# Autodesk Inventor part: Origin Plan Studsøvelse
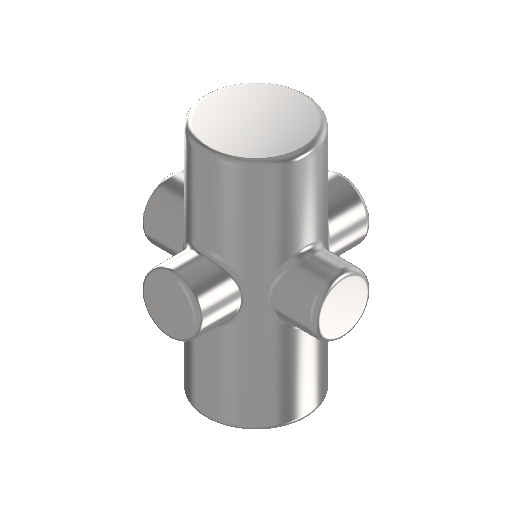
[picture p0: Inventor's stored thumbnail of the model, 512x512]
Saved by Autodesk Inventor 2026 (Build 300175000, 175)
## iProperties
Created: 2004-09
Part Number: Origin Plan Studsøvelse
Document SubType Name: Modeling
Designer: Lars Bertram Pedersen
Manufacturer: Standard
Standards Organization: Custom
Material: Steel, Mild
Density: 7.85 g/cm^3
Appearance: Semi-Polished
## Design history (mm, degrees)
sketch "Sketch1"
  geometry: C1 r 17.5 at (0, 0)
  constraints: 1 centre point
  dimensions: "d0" = 35 diameter of C1
extrude "Extrusion1" new body sketch "Sketch1" stored distance "d1" = 80; taper "d2" = 0 deg
sketch "Sketch2"
  geometry: C1 r 10 at (0, 0); 1 further point
  constraints: 1 centre point, 1 coincident
  dimensions: "d3" = 20 diameter of C1
extrude "Extrusion2" join sketch "Sketch2" stored distance "d4" = 60; taper "d5" = 0 deg
sketch "Sketch3"
  geometry: C1 r 10 at (0, 0); 1 further point
  constraints: 1 centre point, 1 coincident
  dimensions: "d6" = 20 diameter of C1
extrude "Extrusion3" join sketch "Sketch3" stored distance "d7" = 60; taper "d8" = 0 deg
fillet "Fillet1" dims "d9" = 2, "d10" = 2
body "Solid1"
